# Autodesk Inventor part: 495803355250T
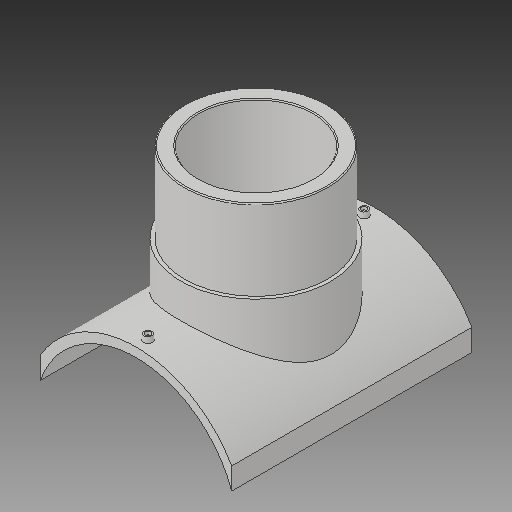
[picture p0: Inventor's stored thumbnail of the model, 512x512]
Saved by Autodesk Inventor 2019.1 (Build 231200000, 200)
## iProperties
Created: 2017-10
Part Number: 495803355250T
Material: Generic
Description: PLASSON BRANCH SADDLE  355x250
Document SubType Name: Modeling
Designer: KIM
Mass: 2754.05 g
Surface Area: 3037.44 cm^2
Volume: 2754.05 cm^3
Density: 1 g/cm^3
Appearance: Default
Author: KIM
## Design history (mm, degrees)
derived "495803.ipt"
feature "Solid1::495803.ipt"
tag "TaggingFeature1"
body "Solid1"
other parameters: "d0" = 355, "d1" = 16, "d2" = 335, "d4" = 0, "d12" = 203.1, "d13" = 14, "d14" = 189, "d16" = 5 deg, "d18" = 4, "d19" = 14, "d20" = 0, "d21" = 3, "d22" = 0, "d23" = 393.5, "d24" = 262.5, "d25" = 16, "d28" = 0, "d29" = 9.6, "d31" = 0, "d33" = 0, "d34" = 3.55, "d38" = 0, "d39" = 1.775, "d_" = 355, "B_" = 335, "x_" = 16, "D_" = 16
